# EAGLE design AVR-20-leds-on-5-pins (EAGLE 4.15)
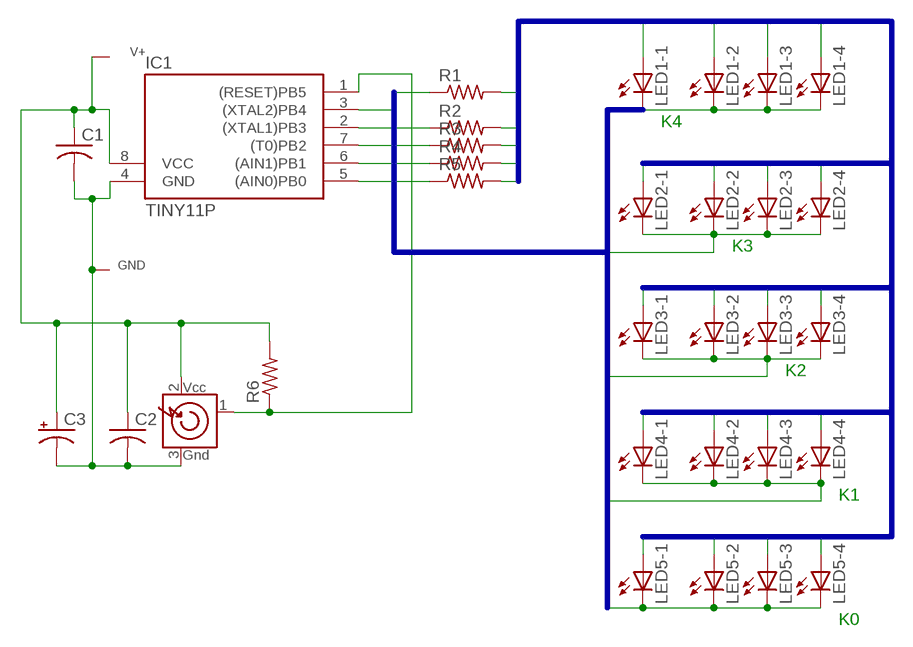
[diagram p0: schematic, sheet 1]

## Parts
C1  C-US-AX075  [C075-AXIAL]
C2  C-US025-025X050  [C025-025X050]
C3  CPOL-USE3.5-8  [E3,5-8]
GND  WIRE  [GENERIC1]
IC1  TINY11P  [DIL08]
LED1-1  LED5MM  [LED5MM]
LED1-2  LED5MM  [LED5MM]
LED1-3  LED5MM  [LED5MM]
LED1-4  LED5MM  [LED5MM]
LED2-1  LED5MM  [LED5MM]
LED2-2  LED5MM  [LED5MM]
LED2-3  LED5MM  [LED5MM]
LED2-4  LED5MM  [LED5MM]
LED3-1  LED5MM  [LED5MM]
LED3-2  LED5MM  [LED5MM]
LED3-3  LED5MM  [LED5MM]
LED3-4  LED5MM  [LED5MM]
LED4-1  LED5MM  [LED5MM]
LED4-2  LED5MM  [LED5MM]
LED4-3  LED5MM  [LED5MM]
LED4-4  LED5MM  [LED5MM]
LED5-1  LED5MM  [LED5MM]
LED5-2  LED5MM  [LED5MM]
LED5-3  LED5MM  [LED5MM]
LED5-4  LED5MM  [LED5MM]
R1  R-US_0207/10  [0207/10]
R2  R-US_0207/10  [0207/10]
R3  R-US_0207/12  [0207/12]
R4  R-US_0207/10  [0207/10]
R5  R-US_0207/10  [0207/10]
R6  R-US_0207/10  [0207/10]
U$1  IRRECVV  [IR-RCVR-V]
V+  WIRE  [GENERIC1]

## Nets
A0: LED1-1.A LED2-1.A LED3-1.A LED4-1.A R5.2
A1: LED1-2.A LED2-2.A LED3-2.A LED5-1.A R4.2
A2: LED1-3.A LED2-3.A LED4-2.A LED5-2.A R3.2
A3: LED1-4.A LED3-3.A LED4-3.A LED5-3.A R2.2
A4: LED2-4.A LED3-4.A LED4-4.A LED5-4.A R1.2
GND: C1.P$2 C2.2 C3.- GND.P$2 IC1.4(GND) U$1.3(GND)
K0: IC1.7((T0)PB2) LED5-1.K(C) LED5-2.K(C) LED5-3.K(C) LED5-4.K(C) R5.1
K1: IC1.6((AIN1)PB1) LED4-1.K(C) LED4-2.K(C) LED4-3.K(C) LED4-4.K(C) R4.1
K2: IC1.5((AIN0)PB0) LED3-1.K(C) LED3-2.K(C) LED3-3.K(C) LED3-4.K(C) R3.1
K3: IC1.3((XTAL2)PB4) LED2-1.K(C) LED2-2.K(C) LED2-3.K(C) LED2-4.K(C) R2.1
K4: IC1.2((XTAL1)PB3) LED1-1.K(C) LED1-2.K(C) LED1-3.K(C) LED1-4.K(C) R1.1
N$2: IC1.1((RESET)PB5) R6.1 U$1.1(OUT)
V+: C1.P$1 C2.1 C3.+ IC1.8(VCC) R6.2 U$1.2(VCC) V+.P$2

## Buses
K[0..4]
A[0..4]

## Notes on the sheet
- K4
- K3
- K2
- K1
- K0

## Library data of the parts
C1 = my-rcl:C-US: CAPACITOR, American symbol
C2 = rcl:C-US: CAPACITOR, American symbol
C3 = rcl:CPOL-US: POLARIZED CAPACITOR, American symbol
GND V+ = mylib:WIRE: Pad for a wire offboard
IC1 = atmel:TINY11*: MICROCONTROLLER 1 Kbytes FLASH
LED1-1-LED1-4 LED2-1-LED2-4 LED3-1-LED3-4 LED4-1-LED4-4 LED5-1-LED5-4 = led:LED: LED
R1-R6 = rcl:R-US_: RESISTOR, American symbol
U$1 = mylib:IRRECV: IR Reciver. Integrated for remote control. Vishay TSOP28

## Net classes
0 default: width 0.6 mm
1 power: width 1 mm

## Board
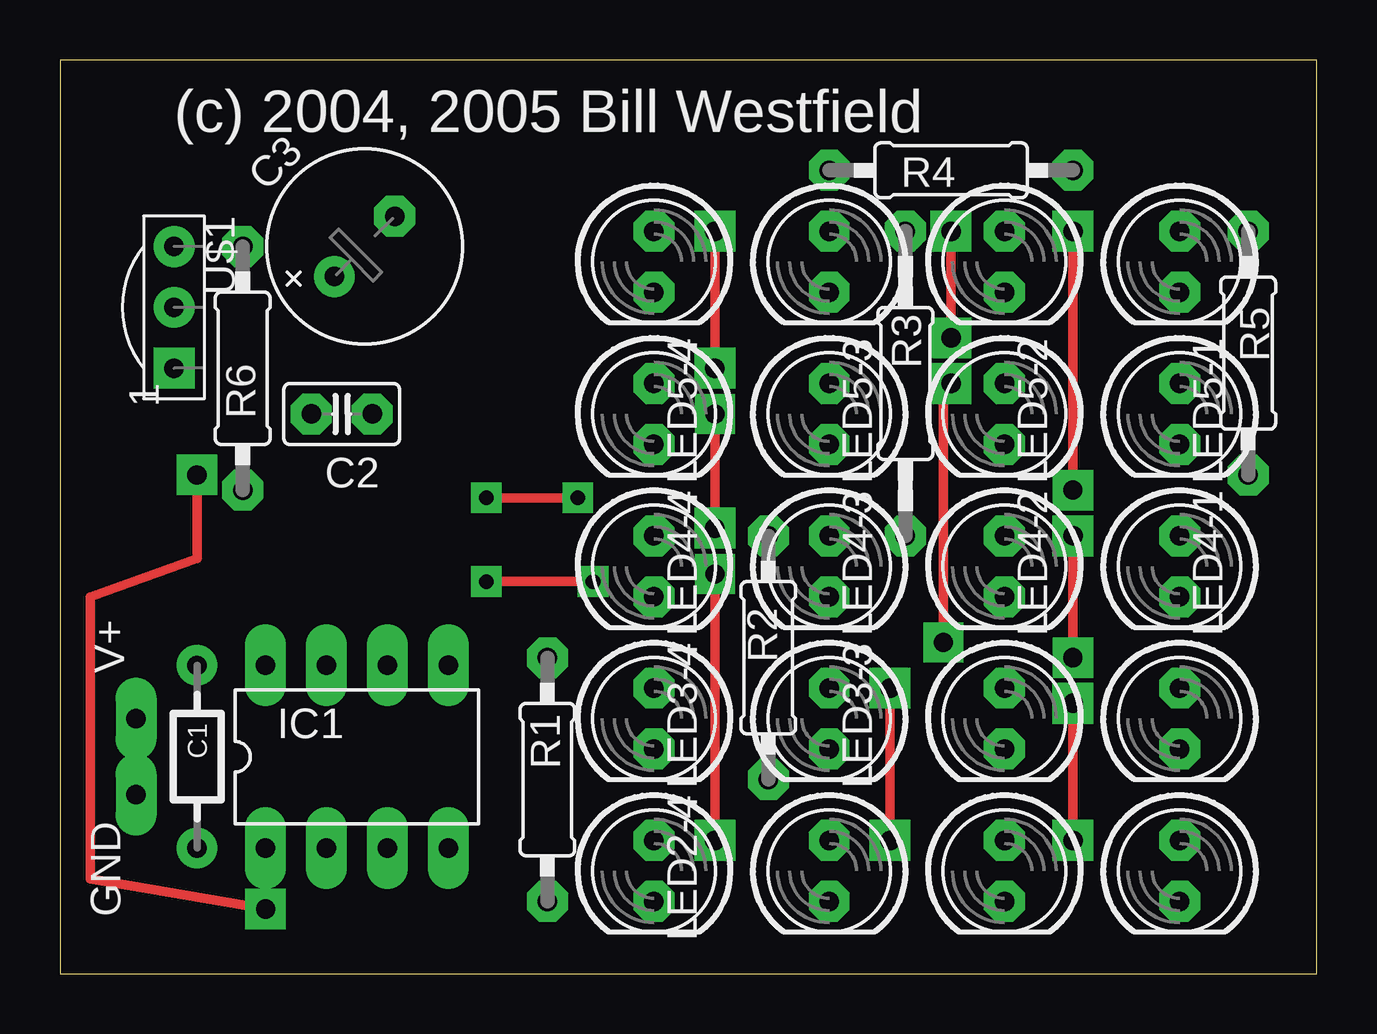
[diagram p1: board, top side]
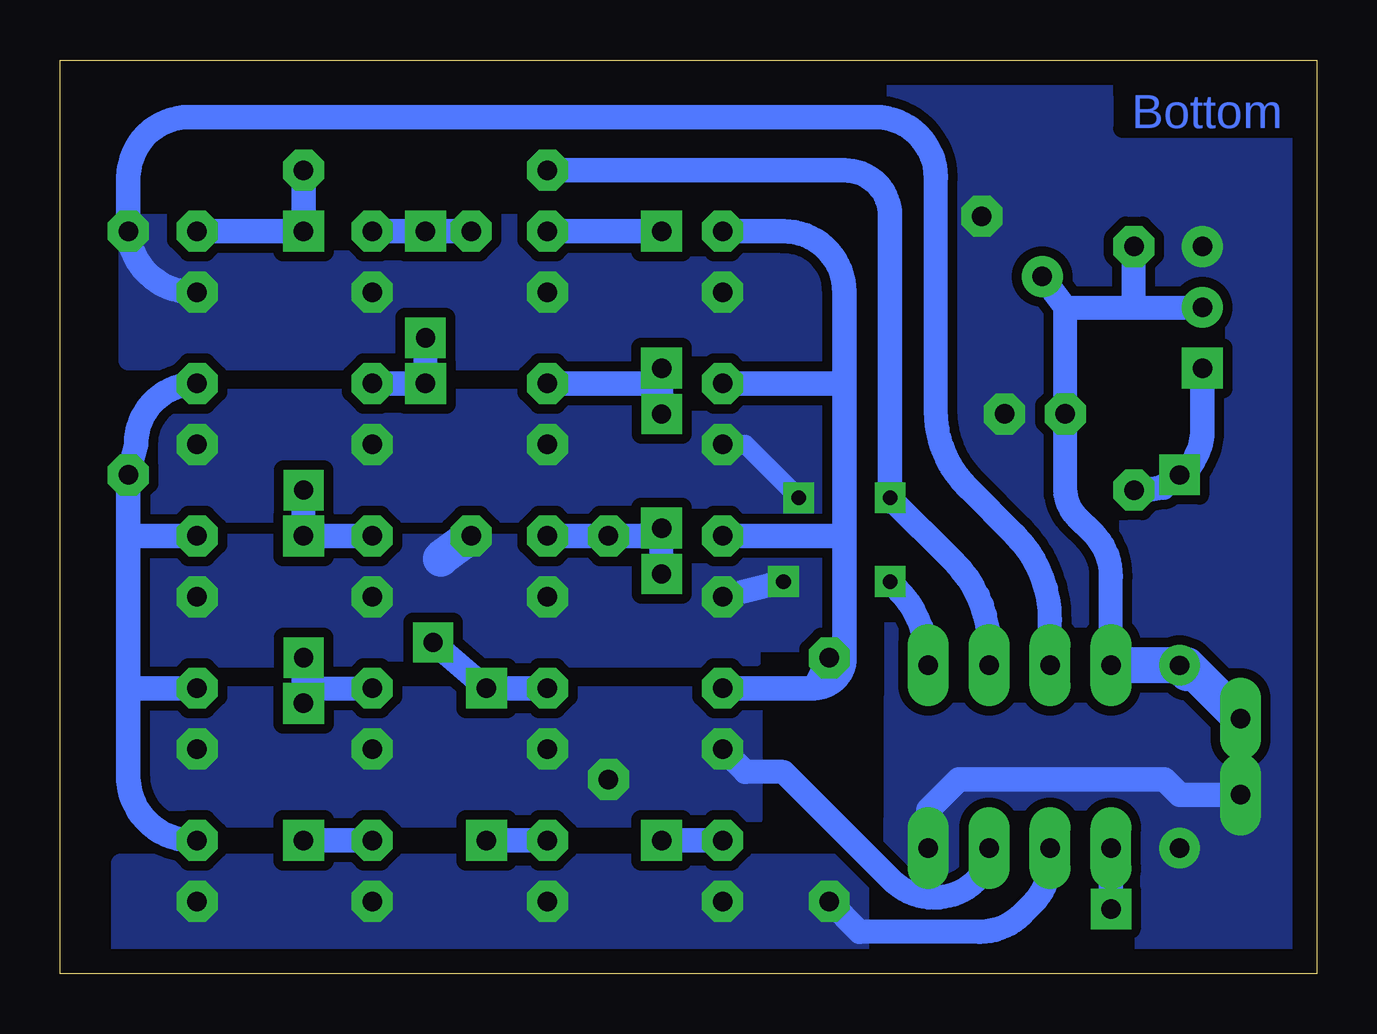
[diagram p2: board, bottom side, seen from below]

Size 52.38 x 38.09 mm. Coordinates in mm from the lower left corner, seen from the top.
Outline: 52.38,0 52.38,38.09 0,38.09 0,0 52.38,0
Copper layers (1*16): Top 0.035mm / dielectric 1.5mm / Bottom 0.035mm
Design rules "default": minimum track width 10mil, minimum drill 24mil, track to track 0.3mm, track to pad 0.4mm, pad to pad 0.4mm, via to via 0.4mm, smd to smd 8mil, copper to edge 40mil, drill to drill 8mil, minimum pad ring 10mil, minimum via ring 8mil, stop-mask expansion 4mil, vias tented up to drill 0mil, thermal gap 10mil

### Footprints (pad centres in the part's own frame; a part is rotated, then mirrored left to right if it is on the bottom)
C075-AXIAL = drill 0.8 round: P$1 -3.81,0; P$2 3.81,0
C025-025X050 = drill 0.813 octagon: 1 -1.27,0; 2 1.27,0
E3,5-8 = drill 0.813 pad 1.6 round: + -1.778,0 | drill 0.813 pad 1.6 octagon: - 1.778,0
GENERIC1 = drill 0.813 long: P$2 0,0
DIL08 = drill 0.813 long: 1 -3.81,-3.81; 2 -1.27,-3.81; 3 1.27,-3.81; 4 3.81,-3.81; 5 3.81,3.81; 6 1.27,3.81; 7 -1.27,3.81; 8 -3.81,3.81
LED5MM = drill 0.813 octagon: A -1.27,0; K 1.27,0
0207/10 = drill 0.813 octagon: 1 -5.08,0; 2 5.08,0
0207/12 = drill 0.813 octagon: 1 -6.35,0; 2 6.35,0
IR-RCVR-V = drill 0.813 square: 1 2.54,0 | drill 0.813 round: 2 0,0; 3 -2.54,0

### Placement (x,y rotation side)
C1  5.71,9.04 270 top
C2  11.74,23.33 0 top
C3  12.7,30.32 45 top
GND  3.17,7.46 270 top
IC1  12.38,9.04 0 top
LED1-1  46.67,4.28 270 top
LED1-2  39.37,4.28 270 top
LED1-3  32.06,4.28 270 top
LED1-4  24.76,4.28 270 top
LED2-1  46.67,10.63 270 top
LED2-2  39.37,10.63 270 top
LED2-3  32.06,10.63 270 top
LED2-4  24.76,10.63 270 top
LED3-1  46.67,16.98 270 top
LED3-2  39.37,16.98 270 top
LED3-3  32.06,16.98 270 top
LED3-4  24.76,16.98 270 top
LED4-1  46.67,23.33 270 top
LED4-2  39.37,23.33 270 top
LED4-3  32.06,23.33 270 top
LED4-4  24.76,23.33 270 top
LED5-1  46.67,29.68 270 top
LED5-2  39.37,29.68 270 top
LED5-3  32.06,29.68 270 top
LED5-4  24.76,29.68 270 top
R1  20.32,8.09 90 top
R2  29.52,13.17 90 top
R3  35.24,24.6 90 top
R4  37.14,33.49 0 top
R5  49.52,25.87 270 top
R6  7.61,25.23 90 top
U$1  4.76,27.77 270 top
V+  3.17,10.63 270 top

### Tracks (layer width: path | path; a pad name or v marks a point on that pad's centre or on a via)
A0
  Bottom 1.016: LED1-1.A arc90 49.52,8.09 49.52,11.9 | 49.52,11.9 LED2-1.A | 49.52,18.25 LED3-1.A | 49.52,11.9 49.52,18.25 | 49.52,18.25 R5.2 49.21,22.06 arc90 LED4-1.A
A1  (via drill 0.8, 0.81)
  Top 0.4: v42.22,20.16 v42.22,30.95 | v42.22,13.17 v42.22,18.25 | v42.22,5.55 v42.22,11.26
  Bottom 1: v42.22,18.25 v42.22,20.16 | 42.22,11.9 LED2-2.A | v42.22,11.26 42.22,11.9 | 42.22,11.9 v42.22,13.17
  Bottom 1.016: LED1-2.A v42.22,5.55 | v42.22,18.25 LED3-2.A | LED5-1.A v42.22,30.95 R4.2
A2  (via drill 0.8, 0.81)
  Top 0.4: v37.14,26.5 v37.14,30.95 | v36.83,13.81 36.83,24.28 | v34.6,5.55 v34.6,11.9
  Top 1: 36.83,24.28 v37.14,24.6
  Bottom 1: v37.14,24.6 v37.14,26.5 | v34.6,11.9 v36.83,13.81
  Bottom 1.016: LED1-3.A v34.6,5.55 | R3.2 v37.14,30.95 R3.2 | R3.2 LED5-2.A | v34.6,11.9 LED2-3.A | v37.14,24.6 LED4-2.A
A3  (via drill 0.8, 0.81)
  Top 0.4: v27.3,25.23 v27.3,30.95 | v27.3,18.57 v27.3,23.33 | v27.3,5.55 v27.3,16.66
  Bottom 1: v27.3,23.33 27.3,24.6 | v27.3,16.66 v27.3,18.57
  Bottom 1.016: LED1-4.A v27.3,5.55 | v27.3,18.57 27.3,18.25 R2.2 LED3-3.A | v27.3,25.23 27.3,24.6 LED4-3.A | v27.3,30.95 LED5-3.A
A4
  Bottom 1.016: 19.68,18.25 LED3-4.A | 19.68,18.25 19.68,24.6 | 19.68,24.6 LED4-4.A | 19.68,24.6 19.68,28.41 arc-90 22.22,30.95 LED5-4.A | 20.95,11.9 LED2-4.A | 19.68,13.17 arc90 20.95,11.9 | 19.68,13.17 19.68,18.25 | R1.2 19.68,13.17 | R1.2 20.95,11.9 | R1.2 20.32,12.53
GND
  Bottom 1.016: GND.P$2 5.71,7.46 6.34,8.09 14.92,8.09 16.19,6.82 IC1.4
  pour Bottom (isolate 0.4, no thermals): -1.59,-1.12 -1.59,39.52 17.62,39.52 17.78,-1.12
K0
  Bottom 1: 15.87,23.49 arc90 15.87,23.49 | IC1.7 11.11,14.75 arc-45 12.57,18.29 14.52,20.24 arc45 15.87,23.49 | 15.87,23.49 arc-44 15.87,23.49 | 15.87,23.49 15.87,33.17
  Bottom 1.016: LED5-1.K arc90 R5.1 49.52,33.17 arc90 46.98,35.71 18.41,35.71 arc90 15.87,33.17
  pour Bottom (isolate 0.406, no thermals): 19.68,25.55 49.52,25.55 49.52,31.27 19.68,31.27
K1  (via drill 0.6)
  Top 0.4: v17.78,19.84 v21.58,19.84
  Bottom 0.8: LED4-4.K 23.81,22.06 v21.58,19.84
  Bottom 1: IC1.6 13.65,13.64 arc-45 15.11,17.17 v17.78,19.84
  Bottom 1.016: R4.1 19.68,33.49 arc90 17.78,31.59 v17.78,19.84 17.78,19.68
  pour Bottom (isolate 0.406, no thermals): 19.68,19.2 48.26,19.2 48.26,23.96 19.68,23.96
K2  (via drill 0.61)
  Top 0.4: v17.78,16.34 v22.22,16.34
  Bottom 1: IC1.5 arc-45 17.53,16.1 v17.78,16.34
  Bottom 1.016: v22.22,16.34 LED3-4.K
  Bottom 1.5: R3.1 36.51,17.3
  pour Bottom (isolate 0.406, no thermals): 23.49,13.17 49.52,13.17 49.84,17.93 19.68,17.93 19.68,13.81 24.12,13.81
K3
  Bottom 1: IC1.3 arc52 14.4,3.7 arc38 15.93,3.17 15.95,3.17 arc45 17.71,3.9 22.22,8.41 23.81,8.41 LED2-4.K
  pour Bottom (isolate 0.406, no thermals): 23.49,6.5 49.52,6.5 49.52,11.58 23.49,11.58
K4
  Bottom 1: IC1.2 11.11,4.68 arc45 11.84,2.91 12.28,2.47 arc45 14.05,1.74 19.05,1.74 R1.1
  pour Bottom (isolate 0.406, no thermals): 19.05,0.15 49.84,0.15 49.84,4.6 19.05,4.6
N$2  (via drill 0.8)
  Top 0.4: v8.57,2.69 1.27,3.96 1.27,15.71 5.71,17.3 v5.71,20.79
  Bottom 0.8: v5.71,20.79 6.34,20.16 R6.1
  Bottom 1.016: R6.1 7.3,20.16 arc-90 4.76,22.7 U$1.1 | v8.57,2.69 IC1.1
V+
  Bottom 1: 10.47,27.77 7.61,27.77 | 7.61,27.77 U$1.2 | 10.47,27.77 C2.1 10.47,20.19 arc-45 10,19.04 9.31,18.36 arc45 8.57,16.56 IC1.8 | 7.61,27.77 R6.2 | C3.+ 10.47,27.79 10.47,27.77
  Bottom 1.5: V+.P$2 5.23,12.69 | 5.23,12.69 5.39,12.85 | IC1.8 C1.P$1 5.39,12.85 | 5.39,12.69 5.39,12.53 | 5.23,12.69 5.39,12.69 | 5.39,12.85 5.39,12.69

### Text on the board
Bottom: Bottom
tPlace: (c) 2004, 2005 Bill Westfield
tDocu: pseudo-single-sided. | replace upper traces | with jumpers using | extra vias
